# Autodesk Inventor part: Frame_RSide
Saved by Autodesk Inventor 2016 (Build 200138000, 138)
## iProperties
Created: 2015-11
Part Number: Frame_RSide
Material: Generic
Document SubType Name: Modeling
Designer: John
Density: 1 g/cm^3
Appearance: Default
Author: John
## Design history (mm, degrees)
feature "SOLID1"
body "Solid1"
